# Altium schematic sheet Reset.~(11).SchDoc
size A4
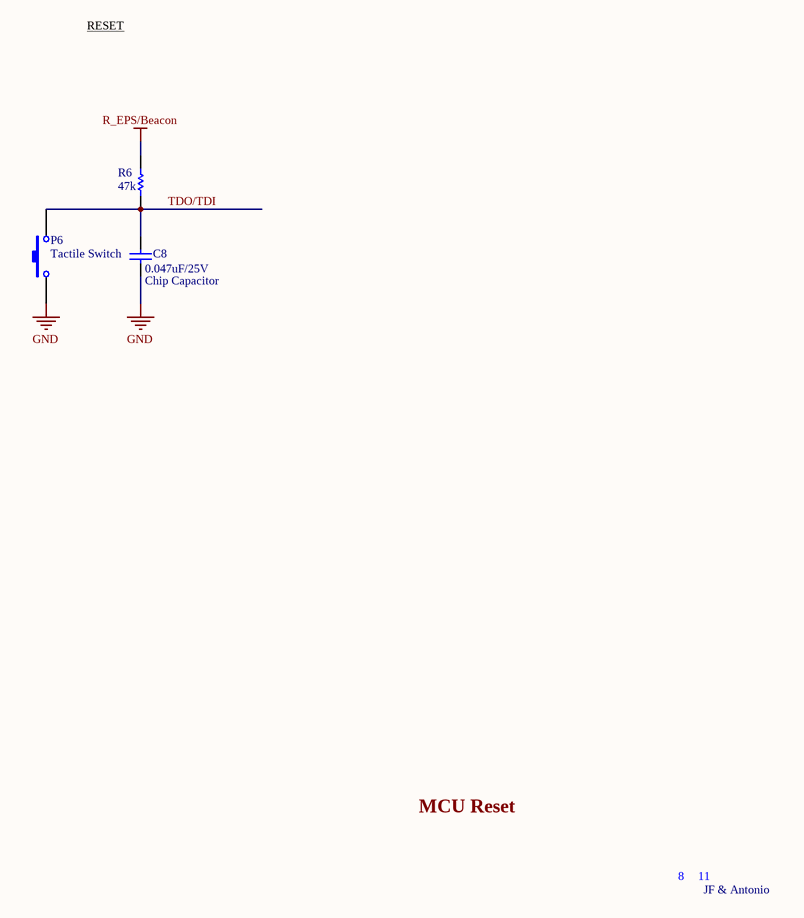
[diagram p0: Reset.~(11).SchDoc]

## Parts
C8  value 0.047uF/25V  PackageDescription: Chip Capacitor  [C0.047u]
P6  Tactile Switch  [SPST-2]
R6  47k  [R47k]

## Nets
GND: C8.2 P6.1
R_EPS/Beacon: R6.2
TDO/TDI: C8.1 P6.2 R6.1

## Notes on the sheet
- RESET
- MCU Reset
- 8
- 11
- JF & Antonio

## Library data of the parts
C8 = Cap Semi: Capacitor (Semiconductor SIM Model)
P6 = SW-PB: Switch
R6 = Res1: Resistor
